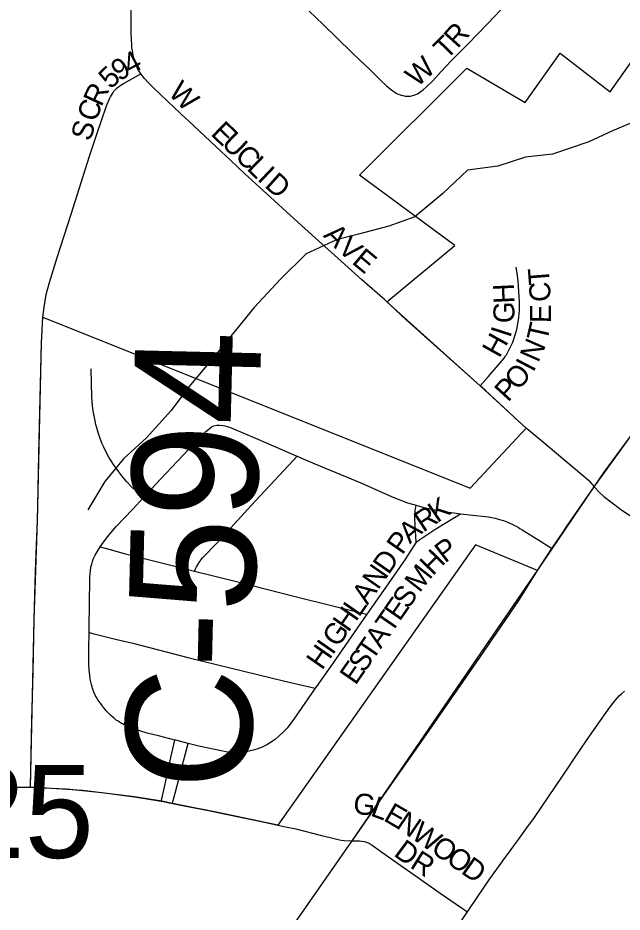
# Model space of a CAD drawing. Extents: x 0 to 34, y 0 to 22.
# Drawn here: x 5.2041 to 5.3403, y 18.1359 to 18.3375 of the extents above; entities that cross this region are included whole.
import ezdxf

# ---------------------------------------------------------------- set-up
doc = ezdxf.new("R2010")
doc.units = 0
for name, color, linetype in [('Default', 7, 'Continuous'), ('GM_X_City_Street', 7, 'Continuous'), ('GM_X_City_Street_Text', 7, 'Continuous'), ('GM_X_Corporation', 7, 'Continuous'), ('GM_X_County_Road', 7, 'Continuous'), ('GM_X_County_Road_Text', 7, 'Continuous'), ('GM_X_Minor_River', 7, 'Continuous'), ('GM_X_Section_Text', 7, 'Continuous'), ('GM_X_State_Route', 7, 'Continuous')]:
    doc.layers.add(name, color=color, linetype=linetype)

msp = doc.modelspace()

# ---------------------------------------------------------------- linework, layer by layer
at = {"layer": 'Default'}
msp.add_lwpolyline([(5.32122, 18.21295), (5.33402, 18.2318), (5.34318, 18.24455), (5.36283, 18.27403), (5.38306, 18.30374), (5.39246, 18.31816)], dxfattribs=at)
at = {"layer": 'GM_X_City_Street'}
for points in [[(5.23181, 18.32496), (5.23143, 18.32555), (5.23108, 18.32616), (5.2308, 18.32675), (5.23053, 18.32748), (5.23031, 18.32822), (5.2301, 18.32911), (5.2299, 18.33018), (5.22981, 18.33083), (5.22974, 18.33157), (5.22963, 18.33388), (5.22961, 18.3371), (5.22973, 18.34147), (5.2299, 18.3458), (5.23022, 18.35696), (5.2304, 18.36471), (5.23048, 18.3672), (5.23051, 18.36844), (5.23052, 18.36906), (5.23059, 18.37059), (5.23071, 18.37392)], [(5.29316, 18.32001), (5.2938, 18.32024), (5.29417, 18.32043), (5.29471, 18.32079), (5.29555, 18.32142), (5.29625, 18.32198), (5.29768, 18.32335), (5.29955, 18.32544), (5.30187, 18.32791), (5.30334, 18.32942), (5.30553, 18.3316), (5.30994, 18.33621), (5.31288, 18.33929), (5.31498, 18.34148), (5.31707, 18.34371), (5.31822, 18.3449)], [(5.26979, 18.33907), (5.2729, 18.33607), (5.27601, 18.33306), (5.27948, 18.32964), (5.28115, 18.32799), (5.28326, 18.32602), (5.28486, 18.32446), (5.28601, 18.32338), (5.28721, 18.32226), (5.288, 18.32157), (5.28864, 18.32109), (5.28911, 18.32076), (5.2894, 18.32058), (5.2895, 18.32052), (5.28964, 18.32045), (5.28988, 18.32034), (5.29025, 18.3202), (5.29048, 18.32012), (5.29062, 18.32009), (5.2908, 18.32005), (5.29123, 18.31995), (5.2914, 18.31992), (5.29155, 18.3199), (5.29175, 18.31988), (5.29201, 18.31988), (5.29231, 18.31988), (5.29265, 18.31991), (5.29316, 18.32001)], [(5.22644, 18.32175), (5.22645, 18.32176), (5.22688, 18.32209), (5.22709, 18.32225), (5.22732, 18.32239), (5.22768, 18.32261), (5.22804, 18.32281), (5.22856, 18.32309), (5.23181, 18.32496)], [(5.30833, 18.25461), (5.30069, 18.26146), (5.29164, 18.26947), (5.2868, 18.27395), (5.28167, 18.27846), (5.27624, 18.28335), (5.27114, 18.28796), (5.26721, 18.2915), (5.26193, 18.29633), (5.25941, 18.29863), (5.25529, 18.30241), (5.2521, 18.30537), (5.24868, 18.30854), (5.24257, 18.3143), (5.2419, 18.31495), (5.2394, 18.31728), (5.23466, 18.32178), (5.23355, 18.32292), (5.23265, 18.3239), (5.23181, 18.32496)], [(5.22395, 18.31747), (5.22396, 18.3175), (5.22419, 18.3181), (5.22472, 18.31928), (5.22498, 18.31977), (5.22555, 18.32072), (5.22574, 18.321), (5.22596, 18.32125), (5.22618, 18.32149), (5.22644, 18.32175)], [(5.20997, 18.27236), (5.21047, 18.27516), (5.2112, 18.27786), (5.21296, 18.2835), (5.21613, 18.29327), (5.22026, 18.30634), (5.2218, 18.31107), (5.22299, 18.31461), (5.22395, 18.31747)], [(5.30833, 18.25461), (5.31016, 18.25658), (5.31331, 18.2603), (5.3137, 18.26082), (5.31407, 18.26136), (5.31423, 18.2616), (5.3145, 18.26204), (5.31472, 18.26245), (5.31504, 18.26308), (5.31566, 18.26442), (5.31586, 18.26492), (5.3161, 18.26561), (5.31638, 18.26654), (5.31657, 18.2673), (5.31692, 18.26898), (5.31705, 18.26999), (5.31714, 18.27086), (5.31717, 18.27145), (5.3172, 18.27237), (5.31718, 18.2736), (5.31715, 18.27469), (5.31698, 18.27713), (5.31688, 18.27817), (5.31671, 18.27945), (5.31641, 18.28133)], [(5.23239, 18.22938), (5.23172, 18.22997), (5.23072, 18.23085), (5.22963, 18.23192), (5.22867, 18.23295), (5.22749, 18.23433), (5.22682, 18.23517), (5.22561, 18.23686), (5.2246, 18.23853), (5.22409, 18.23945), (5.22337, 18.24088), (5.22302, 18.24169), (5.22246, 18.24319), (5.22218, 18.24405), (5.22167, 18.24585), (5.22147, 18.24669), (5.22112, 18.24855), (5.22098, 18.24944), (5.22081, 18.25102), (5.22075, 18.25204), (5.22061, 18.25843)], [(5.31873, 18.24504), (5.3161, 18.24743), (5.31237, 18.25089), (5.31171, 18.25153), (5.31057, 18.25257), (5.30944, 18.25362), (5.30833, 18.25461)], [(5.23239, 18.22938), (5.23625, 18.23354), (5.24519, 18.24305), (5.24646, 18.24426), (5.24715, 18.24485), (5.24774, 18.24531), (5.2483, 18.24558), (5.24891, 18.24571), (5.24951, 18.24573), (5.25026, 18.24567), (5.25075, 18.24559), (5.25179, 18.24526), (5.25273, 18.2449), (5.25767, 18.24282), (5.26563, 18.23932), (5.26649, 18.23899), (5.26703, 18.23876)], [(5.33402, 18.2318), (5.33379, 18.23216), (5.3335, 18.23253), (5.3332, 18.23285), (5.33271, 18.23333), (5.33124, 18.23451), (5.32224, 18.24213), (5.31873, 18.24504)], [(5.24392, 18.21281), (5.24422, 18.21346), (5.24438, 18.2138), (5.24457, 18.21416), (5.24488, 18.21467), (5.24515, 18.21509), (5.24536, 18.21537), (5.2458, 18.2159), (5.24894, 18.21915), (5.2567, 18.22763), (5.26613, 18.23778), (5.26703, 18.23876)], [(5.26703, 18.23876), (5.26792, 18.23837), (5.27107, 18.23704), (5.28138, 18.2327), (5.28849, 18.22959), (5.29195, 18.22824), (5.29388, 18.22766)], [(5.33402, 18.2318), (5.33517, 18.23063), (5.33624, 18.22966), (5.33993, 18.22681), (5.34275, 18.22487), (5.34468, 18.22363), (5.34826, 18.22131), (5.34929, 18.22068), (5.34964, 18.2205), (5.34993, 18.22037), (5.35025, 18.22025), (5.35053, 18.22015), (5.35107, 18.22002), (5.35262, 18.21983), (5.35655, 18.21944), (5.35859, 18.2193), (5.36022, 18.21924), (5.36175, 18.21926)], [(5.22264, 18.21829), (5.22299, 18.21879), (5.22427, 18.22051), (5.22627, 18.22289), (5.22991, 18.22671), (5.23239, 18.22938)], [(5.29391, 18.21933), (5.29374, 18.22197), (5.29362, 18.22461), (5.29362, 18.22527), (5.29362, 18.22569), (5.29363, 18.22612), (5.29366, 18.22644), (5.29372, 18.22689), (5.29379, 18.22724), (5.29388, 18.22766)], [(5.29388, 18.22766), (5.29463, 18.22744), (5.29537, 18.22725), (5.29843, 18.22657), (5.29943, 18.22638), (5.30111, 18.22609), (5.30243, 18.22592), (5.30389, 18.22573)], [(5.29391, 18.21933), (5.29408, 18.21948), (5.29431, 18.21965), (5.29449, 18.21978), (5.29722, 18.2216), (5.29835, 18.22232), (5.30084, 18.22384), (5.30389, 18.22573)], [(5.30389, 18.22573), (5.30946, 18.22511), (5.31018, 18.22502), (5.31169, 18.22474), (5.31267, 18.22448), (5.31362, 18.2242), (5.31435, 18.22392), (5.31515, 18.22358), (5.31557, 18.22338), (5.31607, 18.22313), (5.31642, 18.22293), (5.31694, 18.22264), (5.31729, 18.22244), (5.31776, 18.22216), (5.32196, 18.21957), (5.32382, 18.21838), (5.32451, 18.21794)], [(5.29391, 18.21933), (5.29132, 18.21535), (5.28707, 18.20922), (5.28276, 18.20309)], [(5.22017, 18.19897), (5.22023, 18.20663), (5.22028, 18.2098), (5.22032, 18.21156), (5.22036, 18.21229), (5.22042, 18.2129), (5.22056, 18.21369), (5.22073, 18.21442), (5.2209, 18.21499), (5.22109, 18.2155), (5.2215, 18.21639), (5.22195, 18.21718), (5.22263, 18.21827), (5.22264, 18.21829)], [(5.22264, 18.21829), (5.22456, 18.21776), (5.22805, 18.21679), (5.24159, 18.21339), (5.24392, 18.21281)], [(5.24392, 18.21281), (5.25337, 18.21046), (5.26664, 18.20707), (5.2751, 18.20497), (5.28173, 18.20334), (5.28276, 18.20309)], [(5.28276, 18.20309), (5.2826, 18.20287), (5.27519, 18.19213), (5.27142, 18.18681), (5.27115, 18.1864)], [(5.23946, 18.17473), (5.23606, 18.17558), (5.23321, 18.17631), (5.23139, 18.17685), (5.23036, 18.17719), (5.22952, 18.1775), (5.22888, 18.17777), (5.22866, 18.17787), (5.22842, 18.17798), (5.22806, 18.17816), (5.22766, 18.17837), (5.22745, 18.17849), (5.22722, 18.17863), (5.22701, 18.17876), (5.22652, 18.17907), (5.22625, 18.17925), (5.22602, 18.17942), (5.22576, 18.17964), (5.22555, 18.17982), (5.22502, 18.18026), (5.22451, 18.18076), (5.22428, 18.18099), (5.22402, 18.1813), (5.22374, 18.18164), (5.22351, 18.18192), (5.22317, 18.18237), (5.22305, 18.18253), (5.2227, 18.18301), (5.22236, 18.18348), (5.22204, 18.18397), (5.22172, 18.18449), (5.22154, 18.18482), (5.22126, 18.18541), (5.22106, 18.18595), (5.2209, 18.1864), (5.2208, 18.18672), (5.22066, 18.18723), (5.22051, 18.18785), (5.2204, 18.18842), (5.22028, 18.18935), (5.22018, 18.19047), (5.22011, 18.19197), (5.22008, 18.19314), (5.22006, 18.1954), (5.22017, 18.19897)], [(5.22017, 18.19897), (5.22099, 18.19874), (5.22638, 18.19742), (5.23002, 18.19659), (5.24268, 18.19329), (5.26431, 18.18804), (5.27115, 18.1864)], [(5.27115, 18.1864), (5.26647, 18.17966), (5.26477, 18.17744), (5.26381, 18.17642), (5.26311, 18.17576), (5.26207, 18.17488), (5.2608, 18.17402), (5.26025, 18.17369), (5.25915, 18.17313), (5.25799, 18.1727), (5.2574, 18.17253), (5.2562, 18.17224), (5.25559, 18.17213), (5.25446, 18.172), (5.2537, 18.17195), (5.25254, 18.17193), (5.25175, 18.17199), (5.25095, 18.17209), (5.25031, 18.1722), (5.24486, 18.17338), (5.2425, 18.17397)], [(5.30548, 18.13601), (5.30798, 18.13969), (5.31052, 18.14344), (5.31402, 18.14831), (5.31698, 18.15233), (5.31885, 18.15494), (5.32055, 18.15726), (5.32845, 18.16893), (5.32915, 18.16998), (5.33071, 18.17232), (5.33243, 18.17483), (5.33549, 18.17914), (5.33672, 18.18092), (5.33762, 18.18219), (5.33878, 18.18365), (5.33975, 18.18474), (5.3402, 18.18518), (5.34086, 18.18574)], [(5.23641, 18.16094), (5.2366, 18.1618), (5.23719, 18.1645), (5.23859, 18.17083), (5.23946, 18.17473)], [(5.2425, 18.17397), (5.23973, 18.17467), (5.23946, 18.17473)], [(5.23891, 18.16045), (5.23911, 18.16113), (5.23958, 18.16272), (5.24153, 18.17027), (5.24227, 18.1731), (5.2425, 18.17397)], [(5.27949, 18.152), (5.28108, 18.15201), (5.28162, 18.15196), (5.28217, 18.15185), (5.2825, 18.15177), (5.28305, 18.15154), (5.28351, 18.15131), (5.28399, 18.15101), (5.28588, 18.14966), (5.2889, 18.14752), (5.29347, 18.14434), (5.29927, 18.14021), (5.30432, 18.13679), (5.30548, 18.13601)], [(5.26896, 18.08369), (5.27485, 18.09212), (5.28048, 18.1), (5.28863, 18.11149), (5.29236, 18.11686), (5.29865, 18.1259), (5.30349, 18.13315), (5.30548, 18.13601)]]:
    msp.add_lwpolyline(points, dxfattribs=at)
at = {"layer": 'GM_X_Corporation'}
msp.add_lwpolyline([(5.26723, 18.13446), (5.27949, 18.152), (5.32122, 18.21295), (5.30727, 18.21874), (5.26269, 18.15555), (5.24955, 18.15831), (5.24161, 18.15992), (5.23891, 18.16045), (5.23653, 18.16093), (5.2304, 18.16195), (5.21868, 18.16338), (5.20691, 18.16408), (5.20777, 18.20189), (5.20848, 18.22426), (5.20856, 18.22745), (5.20938, 18.2643), (5.20972, 18.27005), (5.30606, 18.2315), (5.31873, 18.24504), (5.30833, 18.25461), (5.28726, 18.27352), (5.30261, 18.28619), (5.28113, 18.30209), (5.30529, 18.32617), (5.31846, 18.31843), (5.32633, 18.32955), (5.33764, 18.3209), (5.35084, 18.33959)], dxfattribs=at)
at = {"layer": 'GM_X_County_Road'}
for points in [[(5.20856, 18.22745), (5.20882, 18.23929), (5.20938, 18.2643), (5.20972, 18.27005), (5.20997, 18.27236)], [(5.20849, 18.22426), (5.20849, 18.22454), (5.20856, 18.22745)], [(5.20818, 18.21674), (5.20849, 18.22426)], [(5.20691, 18.16409), (5.20724, 18.17919), (5.20755, 18.19007), (5.20777, 18.20189), (5.20802, 18.21274), (5.20818, 18.21674)], [(5.17157, 18.16397), (5.18492, 18.16403), (5.19516, 18.16408), (5.20691, 18.16409)], [(5.20691, 18.16409), (5.20992, 18.16396), (5.21493, 18.1637), (5.21868, 18.16338), (5.22301, 18.16292), (5.2304, 18.16195), (5.23641, 18.16094)], [(5.23641, 18.16094), (5.23653, 18.16093), (5.23891, 18.16045)], [(5.23891, 18.16045), (5.24161, 18.15992)], [(5.24161, 18.15992), (5.24782, 18.15869), (5.24955, 18.15831)], [(5.24955, 18.15831), (5.2593, 18.15627), (5.26269, 18.15555), (5.26442, 18.15518), (5.26678, 18.15468), (5.27258, 18.15321), (5.27453, 18.15273), (5.27628, 18.15233), (5.27701, 18.15218), (5.27762, 18.15211), (5.27949, 18.152)]]:
    msp.add_lwpolyline(points, dxfattribs=at)
at = {"layer": 'GM_X_Minor_River'}
msp.add_lwpolyline([(5.34422, 18.31467), (5.33813, 18.31206), (5.3328, 18.30963), (5.32462, 18.30685), (5.31854, 18.30613), (5.31227, 18.30409), (5.30543, 18.3032), (5.29989, 18.29793), (5.29359, 18.29266), (5.2877, 18.29062), (5.28085, 18.28877), (5.27591, 18.28748), (5.26906, 18.28431), (5.26332, 18.27866), (5.25739, 18.27225), (5.24821, 18.26094), (5.24266, 18.25434), (5.23863, 18.24906), (5.23309, 18.24284), (5.22793, 18.23813), (5.22372, 18.23304), (5.21988, 18.22662)], dxfattribs=at)
at = {"layer": 'GM_X_State_Route'}
for points in [[(5.32205, 18.2142), (5.32451, 18.21794), (5.3268, 18.22132), (5.32797, 18.22305), (5.33402, 18.2318), (5.33632, 18.23512), (5.34318, 18.24455)], [(5.27949, 18.152), (5.28038, 18.15327), (5.28781, 18.164), (5.29493, 18.1742), (5.30828, 18.19331), (5.31702, 18.20616), (5.32122, 18.21295), (5.32205, 18.2142)], [(5.25071, 18.11074), (5.25689, 18.11963), (5.25813, 18.12142), (5.2672, 18.13442), (5.26723, 18.13446), (5.27949, 18.152)]]:
    msp.add_lwpolyline(points, dxfattribs=at)

# ---------------------------------------------------------------- texts
at = {"layer": 'GM_X_City_Street_Text'}
for s, rotation, p in [('R', 48.064, (5.3032, 18.33048)), ('T', 45.4831, (5.30071, 18.32793)), ('4', 28.1294, (5.22935, 18.32462)), ('9', 31.1083, (5.22691, 18.32314)), ('W', 41.9672, (5.2941, 18.32174)), ('5', 43.7191, (5.22502, 18.3213)), ('W', 315, (5.23779, 18.32043)), ('R', 65.2164, (5.22291, 18.31732)), ('C', 71.3654, (5.22176, 18.31389)), ('S', 73.6644, (5.22045, 18.30955)), ('E', 315.9854, (5.24736, 18.31127)), ('U', 316.0186, (5.24976, 18.30895)), ('C', 315.9961, (5.25276, 18.30606)), ('L', 315.9854, (5.25546, 18.30345)), ('I', 316.5122, (5.25789, 18.30111)), ('D', 318.1091, (5.25951, 18.29957)), ('A', 315.17, (5.27279, 18.28834)), ('V', 318.2532, (5.27595, 18.28521)), ('E', 320.1146, (5.27919, 18.28233)), ('T', 94.7191, (5.32407, 18.27754)), ('H', 92.7327, (5.3161, 18.27322)), ('C', 92.6535, (5.32425, 18.27361)), ('G', 87.9211, (5.31595, 18.26862)), ('E', 89.0914, (5.32426, 18.26871)), ('I', 72.1335, (5.31507, 18.26524)), ('T', 77.2052, (5.32339, 18.26439)), ('H', 60.9709, (5.31264, 18.26067)), ('N', 66.2434, (5.32141, 18.25964)), ('O', 49.8691, (5.31697, 18.25336)), ('I', 62.376, (5.32029, 18.25748)), ('P', 47.8016, (5.31461, 18.25075)), ('K', 34.4082, (5.29865, 18.22358)), ('R', 33.5553, (5.29546, 18.22146)), ('A', 41.4738, (5.29247, 18.21881)), ('P', 55.1851, (5.29077, 18.21629)), ('P', 37.4054, (5.30039, 18.21448)), ('D', 55.1583, (5.28767, 18.21184)), ('H', 45.7264, (5.29762, 18.21161)), ('N', 55.1583, (5.28529, 18.20842)), ('M', 52.0371, (5.29464, 18.20778)), ('A', 55.1583, (5.28291, 18.205)), ('S', 55.3454, (5.29207, 18.20407)), ('E', 55.3325, (5.29017, 18.20132)), ('H', 55.1583, (5.27862, 18.19885)), ('L', 55.158, (5.281, 18.20227)), ('T', 55.3454, (5.28827, 18.19858)), ('G', 55.1583, (5.27624, 18.19543)), ('A', 55.3339, (5.2859, 18.19515)), ('I', 55.1583, (5.27505, 18.19372)), ('T', 55.3325, (5.28401, 18.19241)), ('H', 55.1583, (5.27267, 18.1903)), ('S', 55.3454, (5.28211, 18.18967)), ('E', 55.3325, (5.28021, 18.18693)), ('G', 353.0973, (5.27951, 18.1582)), ('L', 339.8885, (5.28337, 18.15776)), ('E', 329.8891, (5.2863, 18.15671)), ('N', 325.8067, (5.28911, 18.15509)), ('W', 324.9295, (5.29254, 18.15275)), ('D', 323.3749, (5.28861, 18.14881)), ('O', 324.9095, (5.29697, 18.14964)), ('O', 324.9198, (5.30038, 18.14725)), ('R', 327.6468, (5.29227, 18.14611)), ('D', 324.9198, (5.30379, 18.14485))]:
    msp.add_text(s, height=0.00473, rotation=rotation, dxfattribs=at).set_placement(p)
at = {"layer": 'GM_X_County_Road_Text'}
msp.add_text('C-594', height=0.028409, rotation=88.6253, dxfattribs=at).set_placement((5.25651, 18.16327))
at = {"layer": 'GM_X_Section_Text'}
msp.add_text('25', height=0.020928, rotation=0, dxfattribs=at).set_placement((5.19008, 18.14816))

doc.saveas('drawing.dxf')
